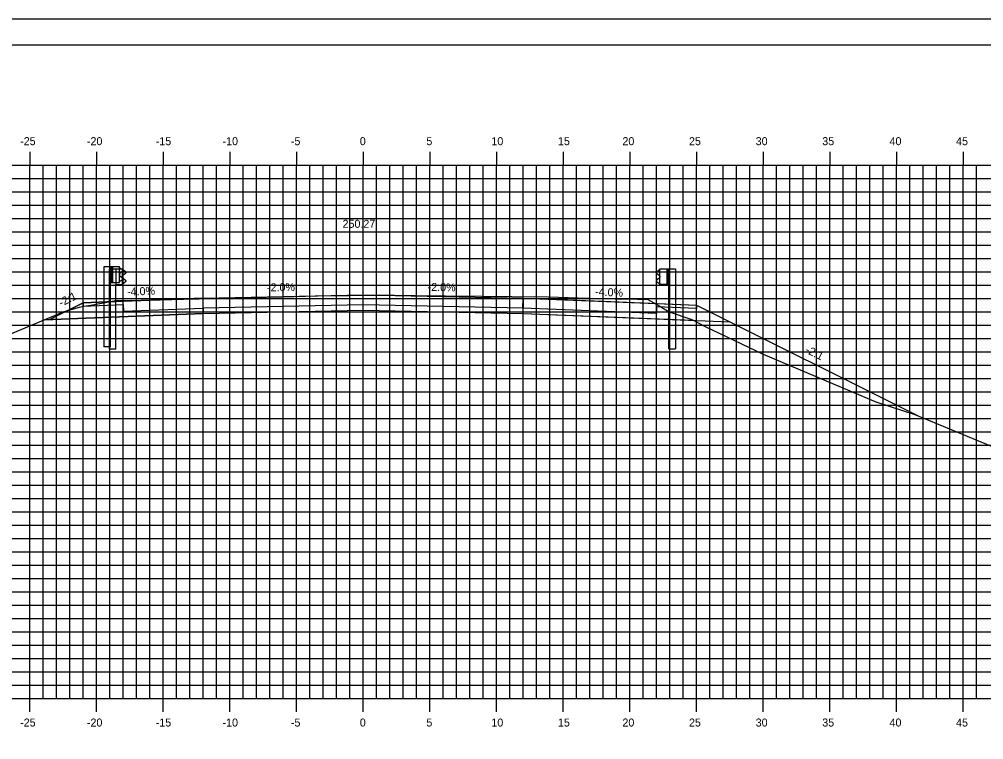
# Model space of a CAD drawing. Extents: x -22 to 1480, y -1511 to 8.
# Drawn here: x 1049.4 to 1121.7, y -1455.4 to -1401.4 of the extents above; entities that cross this region are included whole.
import ezdxf

# ---------------------------------------------------------------- set-up
doc = ezdxf.new("R2010")
doc.units = 0
for name, color, linetype in [('ANNOTATION', 7, 'Continuous'), ('BORDER', 7, 'Continuous'), ('D_Guardrail_Beam_Lt', 7, 'Continuous'), ('D_Guardrail_Beam_Rt', 7, 'Continuous'), ('D_Roadway_Centerline', 7, 'Continuous'), ('D_Roadway_Centerline_Text', 7, 'Continuous'), ('D_Roadway_Edge_Shoulder', 7, 'Continuous'), ('D_Roadway_Edge_TW', 7, 'Continuous'), ('D_Roadway_SlopeLines', 7, 'Continuous'), ('D_Roadway_SubGrade', 7, 'Continuous'), ('H_V ANNOTATION', 7, 'Continuous'), ('MAJOR', 7, 'Continuous'), ('MINOR', 7, 'Continuous'), ('PLOT BOUNDARY', 7, 'Continuous'), ('S_Guardrail_Beam', 7, 'Continuous'), ('S_Roadway_Centerline', 7, 'Continuous')]:
    doc.layers.add(name, color=color, linetype=linetype)

msp = doc.modelspace()

# ---------------------------------------------------------------- linework, layer by layer
at = {"layer": 'BORDER'}
msp.add_line((1160.183, -1403.331), (1000.183, -1403.331), dxfattribs=at)
at = {"layer": 'D_Guardrail_Beam_Lt'}
for p, q in [((1055.753, -1419.957), (1055.753, -1425.957)), ((1056.224, -1419.957), (1055.753, -1419.957)), ((1056.912, -1419.957), (1056.224, -1419.957)), ((1056.224, -1419.957), (1056.224, -1421.124)), ((1056.287, -1419.957), (1056.287, -1421.124)), ((1056.391, -1419.957), (1056.391, -1421.124)), ((1056.912, -1421.124), (1056.912, -1419.957)), ((1056.912, -1420.04), (1056.986, -1420.055)), ((1056.916, -1420.505), (1056.916, -1420.575)), ((1057.145, -1420.305), (1056.95, -1420.441)), ((1057.002, -1420.061), (1057.145, -1420.161)), ((1056.224, -1421.124), (1056.912, -1421.124)), ((1056.245, -1425.957), (1056.245, -1421.124)), ((1056.986, -1421.026), (1056.912, -1421.04)), ((1056.95, -1420.64), (1057.145, -1420.776)), ((1057.145, -1420.919), (1057.002, -1421.019)), ((1056.245, -1425.957), (1055.753, -1425.957))]:
    msp.add_line(p, q, dxfattribs=at)
for centre, major_axis, start_param, end_param in [((1056.995, -1420.505), (-0.0789, 0), 5.323254, 6.283185), ((1056.978, -1420.095), (0.0417, 0), 0.959931, 1.376053), ((1057.095, -1420.233), (0.0877, 0), 5.323254, 7.243116), ((1056.995, -1420.575), (-0.0789, 0), 6.283185, 7.243116), ((1056.978, -1420.985), (0.0417, 0), 4.907132, 5.323254), ((1057.095, -1420.847), (0.0877, 0), 5.323254, 7.243116)]:
    msp.add_ellipse(centre, major_axis=major_axis, ratio=0.995501, start_param=start_param, end_param=end_param, dxfattribs=at)
at = {"layer": 'D_Guardrail_Beam_Rt'}
for p, q in [((1097.363, -1420.221), (1097.22, -1420.321)), ((1097.22, -1420.465), (1097.415, -1420.601)), ((1097.453, -1420.2), (1097.379, -1420.215)), ((1097.453, -1420.117), (1098.141, -1420.117)), ((1097.453, -1421.284), (1097.453, -1420.117)), ((1097.974, -1420.117), (1097.974, -1421.284)), ((1098.078, -1420.117), (1098.078, -1421.284)), ((1098.141, -1420.117), (1098.612, -1420.117)), ((1098.141, -1420.117), (1098.141, -1421.284)), ((1098.612, -1420.117), (1098.612, -1426.117)), ((1097.415, -1420.8), (1097.22, -1420.936)), ((1097.22, -1421.079), (1097.363, -1421.179)), ((1097.379, -1421.186), (1097.453, -1421.2)), ((1097.449, -1420.665), (1097.449, -1420.735)), ((1098.141, -1421.284), (1097.453, -1421.284)), ((1098.12, -1426.117), (1098.12, -1421.284)), ((1098.12, -1426.117), (1098.612, -1426.117))]:
    msp.add_line(p, q, dxfattribs=at)
for centre, major_axis, start_param, end_param in [((1097.27, -1420.393), (-0.0877, 0), 5.323254, 7.243116), ((1097.387, -1420.255), (-0.0417, 0), 4.907132, 5.323254), ((1097.27, -1421.007), (-0.0877, 0), 5.323254, 7.243116), ((1097.387, -1421.145), (-0.0417, 0), 0.959931, 1.376053), ((1097.37, -1420.665), (0.0789, 0), 0, 0.959931), ((1097.37, -1420.735), (0.0789, 0), 5.323254, 6.283185)]:
    msp.add_ellipse(centre, major_axis=major_axis, ratio=0.995501, start_param=start_param, end_param=end_param, dxfattribs=at)
at = {"layer": 'D_Roadway_Centerline'}
msp.add_lwpolyline([(1053.046, -1423.229), (1054.183, -1422.66), (1057.183, -1422.54), (1063.183, -1422.3), (1075.183, -1422.06), (1087.183, -1422.3), (1097.183, -1422.7), (1100.183, -1422.82), (1116.765, -1431.111)], dxfattribs=at)
at = {"layer": 'D_Roadway_Edge_Shoulder'}
for points in [[(1063.183, -1422.3), (1057.183, -1422.54), (1057.183, -1422.54), (1054.183, -1422.66), (1054.183, -1422.91), (1057.183, -1422.79), (1057.183, -1422.79), (1057.213, -1423.289), (1063.183, -1423.05)], [(1087.183, -1422.3), (1093.183, -1422.54), (1093.183, -1422.54), (1100.183, -1422.82), (1100.183, -1423.07), (1097.183, -1422.95), (1097.183, -1422.95), (1097.183, -1423.45), (1087.173, -1423.05)]]:
    msp.add_lwpolyline(points, close=True, dxfattribs=at)
at = {"layer": 'D_Roadway_Edge_TW'}
msp.add_lwpolyline([(1063.183, -1423.05), (1063.183, -1422.3), (1075.183, -1422.06), (1087.183, -1422.3), (1087.183, -1423.05), (1075.183, -1422.81)], close=True, dxfattribs=at)
at = {"layer": 'D_Roadway_SlopeLines'}
msp.add_line((1063.183, -1423.45), (1051.289, -1423.926), dxfattribs=at)
for points in [[(1054.183, -1422.66), (1051.682, -1423.91)], [(1051.289, -1423.926), (1063.183, -1423.45), (1075.183, -1423.21), (1087.183, -1423.45), (1102.683, -1424.07)], [(1100.183, -1422.82), (1116.765, -1431.111)]]:
    msp.add_lwpolyline(points, dxfattribs=at)
at = {"layer": 'D_Roadway_SubGrade'}
msp.add_line((1087.183, -1423.45), (1099.975, -1423.962), dxfattribs=at)
msp.add_lwpolyline([(1087.183, -1423.45), (1087.183, -1423.05), (1075.183, -1422.81), (1063.183, -1423.05), (1063.183, -1423.45), (1075.183, -1423.21)], close=True, dxfattribs=at)
at = {"layer": 'MAJOR'}
for p, q in [((1050.183, -1411.329), (1050.183, -1412.331)), ((1055.183, -1411.329), (1055.183, -1412.331)), ((1060.183, -1411.329), (1060.183, -1412.331)), ((1065.183, -1411.329), (1065.183, -1412.331)), ((1070.183, -1411.329), (1070.183, -1412.331)), ((1075.183, -1411.329), (1075.183, -1412.331)), ((1080.183, -1411.329), (1080.183, -1412.331)), ((1085.183, -1411.329), (1085.183, -1412.331)), ((1090.183, -1411.329), (1090.183, -1412.331)), ((1095.183, -1411.329), (1095.183, -1412.331)), ((1100.183, -1411.329), (1100.183, -1412.331)), ((1105.183, -1411.329), (1105.183, -1412.331)), ((1110.183, -1411.329), (1110.183, -1412.331)), ((1115.183, -1411.329), (1115.183, -1412.331)), ((1120.183, -1411.329), (1120.183, -1412.331)), ((1005.183, -1412.331), (1145.183, -1412.331)), ((1005.183, -1412.331), (1145.183, -1412.331)), ((1050.183, -1452.331), (1050.183, -1412.331)), ((1055.183, -1452.331), (1055.183, -1412.331)), ((1060.183, -1452.331), (1060.183, -1412.331)), ((1065.183, -1452.331), (1065.183, -1412.331)), ((1070.183, -1452.331), (1070.183, -1412.331)), ((1075.183, -1452.331), (1075.183, -1412.331)), ((1080.183, -1452.331), (1080.183, -1412.331)), ((1085.183, -1452.331), (1085.183, -1412.331)), ((1090.183, -1452.331), (1090.183, -1412.331)), ((1095.183, -1452.331), (1095.183, -1412.331)), ((1100.183, -1452.331), (1100.183, -1412.331)), ((1105.183, -1452.331), (1105.183, -1412.331)), ((1110.183, -1452.331), (1110.183, -1412.331)), ((1115.183, -1452.331), (1115.183, -1412.331)), ((1120.183, -1452.331), (1120.183, -1412.331)), ((1005.183, -1417.331), (1145.183, -1417.331)), ((1005.183, -1422.331), (1145.183, -1422.331)), ((1005.183, -1427.331), (1145.183, -1427.331)), ((1005.183, -1432.331), (1145.183, -1432.331)), ((1005.183, -1437.331), (1145.183, -1437.331)), ((1005.183, -1442.331), (1145.183, -1442.331)), ((1005.183, -1447.331), (1145.183, -1447.331)), ((1005.183, -1452.331), (1145.183, -1452.331)), ((1005.183, -1452.331), (1145.183, -1452.331)), ((1050.183, -1453.333), (1050.183, -1452.331)), ((1055.183, -1453.333), (1055.183, -1452.331)), ((1060.183, -1453.333), (1060.183, -1452.331)), ((1065.183, -1453.333), (1065.183, -1452.331)), ((1070.183, -1453.333), (1070.183, -1452.331)), ((1075.183, -1453.333), (1075.183, -1452.331)), ((1080.183, -1453.333), (1080.183, -1452.331)), ((1085.183, -1453.333), (1085.183, -1452.331)), ((1090.183, -1453.333), (1090.183, -1452.331)), ((1095.183, -1453.333), (1095.183, -1452.331)), ((1100.183, -1453.333), (1100.183, -1452.331)), ((1105.183, -1453.333), (1105.183, -1452.331)), ((1110.183, -1453.333), (1110.183, -1452.331)), ((1115.183, -1453.333), (1115.183, -1452.331)), ((1120.183, -1453.333), (1120.183, -1452.331))]:
    msp.add_line(p, q, dxfattribs=at)
at = {"layer": 'MINOR'}
for p, q in [((1051.183, -1452.331), (1051.183, -1412.331)), ((1052.183, -1452.331), (1052.183, -1412.331)), ((1053.183, -1452.331), (1053.183, -1412.331)), ((1054.183, -1452.331), (1054.183, -1412.331)), ((1056.183, -1452.331), (1056.183, -1412.331)), ((1057.183, -1452.331), (1057.183, -1412.331)), ((1058.183, -1452.331), (1058.183, -1412.331)), ((1059.183, -1452.331), (1059.183, -1412.331)), ((1061.183, -1452.331), (1061.183, -1412.331)), ((1062.183, -1452.331), (1062.183, -1412.331)), ((1063.183, -1452.331), (1063.183, -1412.331)), ((1064.183, -1452.331), (1064.183, -1412.331)), ((1066.183, -1452.331), (1066.183, -1412.331)), ((1067.183, -1452.331), (1067.183, -1412.331)), ((1068.183, -1452.331), (1068.183, -1412.331)), ((1069.183, -1452.331), (1069.183, -1412.331)), ((1071.183, -1452.331), (1071.183, -1412.331)), ((1072.183, -1452.331), (1072.183, -1412.331)), ((1073.183, -1452.331), (1073.183, -1412.331)), ((1074.183, -1452.331), (1074.183, -1412.331)), ((1076.183, -1452.331), (1076.183, -1412.331)), ((1077.183, -1452.331), (1077.183, -1412.331)), ((1078.183, -1452.331), (1078.183, -1412.331)), ((1079.183, -1452.331), (1079.183, -1412.331)), ((1081.183, -1452.331), (1081.183, -1412.331)), ((1082.183, -1452.331), (1082.183, -1412.331)), ((1083.183, -1452.331), (1083.183, -1412.331)), ((1084.183, -1452.331), (1084.183, -1412.331)), ((1086.183, -1452.331), (1086.183, -1412.331)), ((1087.183, -1452.331), (1087.183, -1412.331)), ((1088.183, -1452.331), (1088.183, -1412.331)), ((1089.183, -1452.331), (1089.183, -1412.331)), ((1091.183, -1452.331), (1091.183, -1412.331)), ((1092.183, -1452.331), (1092.183, -1412.331)), ((1093.183, -1452.331), (1093.183, -1412.331)), ((1094.183, -1452.331), (1094.183, -1412.331)), ((1096.183, -1452.331), (1096.183, -1412.331)), ((1097.183, -1452.331), (1097.183, -1412.331)), ((1098.183, -1452.331), (1098.183, -1412.331)), ((1099.183, -1452.331), (1099.183, -1412.331)), ((1101.183, -1452.331), (1101.183, -1412.331)), ((1102.183, -1452.331), (1102.183, -1412.331)), ((1103.183, -1452.331), (1103.183, -1412.331)), ((1104.183, -1452.331), (1104.183, -1412.331)), ((1106.183, -1452.331), (1106.183, -1412.331)), ((1107.183, -1452.331), (1107.183, -1412.331)), ((1108.183, -1452.331), (1108.183, -1412.331)), ((1109.183, -1452.331), (1109.183, -1412.331)), ((1111.183, -1452.331), (1111.183, -1412.331)), ((1112.183, -1452.331), (1112.183, -1412.331)), ((1113.183, -1452.331), (1113.183, -1412.331)), ((1114.183, -1452.331), (1114.183, -1412.331)), ((1116.183, -1452.331), (1116.183, -1412.331)), ((1117.183, -1452.331), (1117.183, -1412.331)), ((1118.183, -1452.331), (1118.183, -1412.331)), ((1119.183, -1452.331), (1119.183, -1412.331)), ((1121.183, -1452.331), (1121.183, -1412.331)), ((1005.183, -1413.331), (1145.183, -1413.331)), ((1005.183, -1414.331), (1145.183, -1414.331)), ((1005.183, -1415.331), (1145.183, -1415.331)), ((1005.183, -1416.331), (1145.183, -1416.331)), ((1005.183, -1418.331), (1145.183, -1418.331)), ((1005.183, -1419.331), (1145.183, -1419.331)), ((1005.183, -1420.331), (1145.183, -1420.331)), ((1005.183, -1421.331), (1145.183, -1421.331)), ((1005.183, -1423.331), (1145.183, -1423.331)), ((1005.183, -1424.331), (1145.183, -1424.331)), ((1005.183, -1425.331), (1145.183, -1425.331)), ((1005.183, -1426.331), (1145.183, -1426.331)), ((1005.183, -1428.331), (1145.183, -1428.331)), ((1005.183, -1429.331), (1145.183, -1429.331)), ((1005.183, -1430.331), (1145.183, -1430.331)), ((1005.183, -1431.331), (1145.183, -1431.331)), ((1005.183, -1433.331), (1145.183, -1433.331)), ((1005.183, -1434.331), (1145.183, -1434.331)), ((1005.183, -1435.331), (1145.183, -1435.331)), ((1005.183, -1436.331), (1145.183, -1436.331)), ((1005.183, -1438.331), (1145.183, -1438.331)), ((1005.183, -1439.331), (1145.183, -1439.331)), ((1005.183, -1440.331), (1145.183, -1440.331)), ((1005.183, -1441.331), (1145.183, -1441.331)), ((1005.183, -1443.331), (1145.183, -1443.331)), ((1005.183, -1444.331), (1145.183, -1444.331)), ((1005.183, -1445.331), (1145.183, -1445.331)), ((1005.183, -1446.331), (1145.183, -1446.331)), ((1005.183, -1448.331), (1145.183, -1448.331)), ((1005.183, -1449.331), (1145.183, -1449.331)), ((1005.183, -1450.331), (1145.183, -1450.331)), ((1005.183, -1451.331), (1145.183, -1451.331))]:
    msp.add_line(p, q, dxfattribs=at)
at = {"layer": 'PLOT BOUNDARY'}
msp.add_lwpolyline([(992.089, -1511.39), (1162.089, -1511.39), (1162.089, -1401.39), (992.089, -1401.39)], close=True, dxfattribs=at)
at = {"layer": 'S_Guardrail_Beam'}
for p, q in [((1056.155, -1420.119), (1056.155, -1426.119)), ((1056.646, -1420.119), (1056.155, -1420.119)), ((1057.136, -1420.119), (1056.646, -1420.119)), ((1056.646, -1420.119), (1056.646, -1421.285)), ((1057.136, -1421.285), (1057.136, -1420.119)), ((1057.136, -1420.191), (1057.218, -1420.206)), ((1057.378, -1420.456), (1057.183, -1420.592)), ((1057.235, -1420.213), (1057.378, -1420.313)), ((1057.218, -1421.198), (1057.136, -1421.212)), ((1057.149, -1420.656), (1057.149, -1420.747)), ((1057.183, -1420.812), (1057.378, -1420.948)), ((1057.378, -1421.091), (1057.235, -1421.191)), ((1056.646, -1426.119), (1056.646, -1421.285)), ((1056.646, -1421.285), (1057.136, -1421.285)), ((1056.646, -1426.119), (1056.155, -1426.119))]:
    msp.add_line(p, q, dxfattribs=at)
for centre, major_axis, start_param, end_param in [((1057.211, -1420.247), (0.0417, 0), 0.959931, 1.396263), ((1057.328, -1420.384), (0.0877, 0), 5.323254, 7.243116), ((1057.228, -1420.656), (-0.0789, 0), 5.323254, 6.283185), ((1057.228, -1420.747), (-0.0789, 0), 6.283185, 7.243116), ((1057.211, -1421.157), (0.0417, 0), 4.886922, 5.323254), ((1057.328, -1421.019), (0.0877, 0), 5.323254, 7.243116)]:
    msp.add_ellipse(centre, major_axis=major_axis, ratio=0.995501, start_param=start_param, end_param=end_param, dxfattribs=at)
at = {"layer": 'S_Roadway_Centerline'}
msp.add_lwpolyline([(1029.449, -1433.065), (1052.765, -1423.308), (1053.921, -1422.98), (1054.25, -1422.911), (1054.767, -1422.821), (1056.656, -1422.489), (1057.077, -1422.486), (1059.095, -1422.45), (1061.73, -1422.387), (1064.095, -1422.328), (1066.755, -1422.26), (1069.095, -1422.2), (1071.779, -1422.141), (1074.095, -1422.098), (1074.746, -1422.087), (1075.491, -1422.078), (1077.547, -1422.09), (1079.095, -1422.1), (1081.368, -1422.122), (1084.095, -1422.15), (1086.345, -1422.182), (1089.096, -1422.214), (1091.323, -1422.28), (1094.096, -1422.364), (1095.76, -1422.388), (1096.554, -1422.405), (1097.395, -1422.891), (1098.138, -1423.336), (1099.852, -1423.896), (1100.854, -1424.435), (1105.18, -1426.496), (1113.637, -1430.085), (1116.566, -1431.029), (1145.183, -1442.874)], dxfattribs=at)

# ---------------------------------------------------------------- texts
at = {"layer": 'ANNOTATION'}
for s, rotation, p in [('-2.0%', 1.14576, (1067.986, -1421.804)), ('-2.0%', 358.85424, (1080.026, -1421.757)), ('-2:1', 26.56505, (1052.543, -1422.962)), ('-4.0%', 2.29061, (1057.499, -1422.127)), ('-4.0%', 357.70939, (1092.578, -1422.115)), ('-2:1', 333.43495, (1108.297, -1426.359))]:
    msp.add_text(s, height=0.6, rotation=rotation, dxfattribs=at).set_placement(p)
at = {"layer": 'D_Roadway_Centerline'}
for s, p in [('C', (1075.177, -1422.06)), ('L', (1075.183, -1422.068))]:
    msp.add_text(s, height=0.0146, dxfattribs=at).set_placement(p)
at = {"layer": 'D_Roadway_Centerline_Text'}
msp.add_text('250.27', height=0.6, dxfattribs=at).set_placement((1073.647, -1417.028))
at = {"layer": 'H_V ANNOTATION'}
for s, p in [('-25', (1049.468, -1410.831)), ('-20', (1054.476, -1410.831)), ('-15', (1059.639, -1410.831)), ('-10', (1064.647, -1410.831)), ('-5', (1069.773, -1410.831)), ('0', (1074.942, -1410.831)), ('5', (1079.934, -1410.831)), ('10', (1084.808, -1410.831)), ('15', (1089.8, -1410.831)), ('20', (1094.637, -1410.831)), ('25', (1099.629, -1410.831)), ('30', (1104.631, -1410.831)), ('35', (1109.623, -1410.831)), ('40', (1114.669, -1410.831)), ('45', (1119.661, -1410.831)), ('-25', (1049.468, -1454.431)), ('-20', (1054.476, -1454.431)), ('-15', (1059.639, -1454.431)), ('-10', (1064.647, -1454.431)), ('-5', (1069.773, -1454.431)), ('0', (1074.942, -1454.431)), ('5', (1079.934, -1454.431)), ('10', (1084.808, -1454.431)), ('15', (1089.8, -1454.431)), ('20', (1094.637, -1454.431)), ('25', (1099.629, -1454.431)), ('30', (1104.631, -1454.431)), ('35', (1109.623, -1454.431)), ('40', (1114.669, -1454.431)), ('45', (1119.661, -1454.431))]:
    msp.add_text(s, height=0.6, dxfattribs=at).set_placement(p)

doc.saveas('drawing.dxf')
